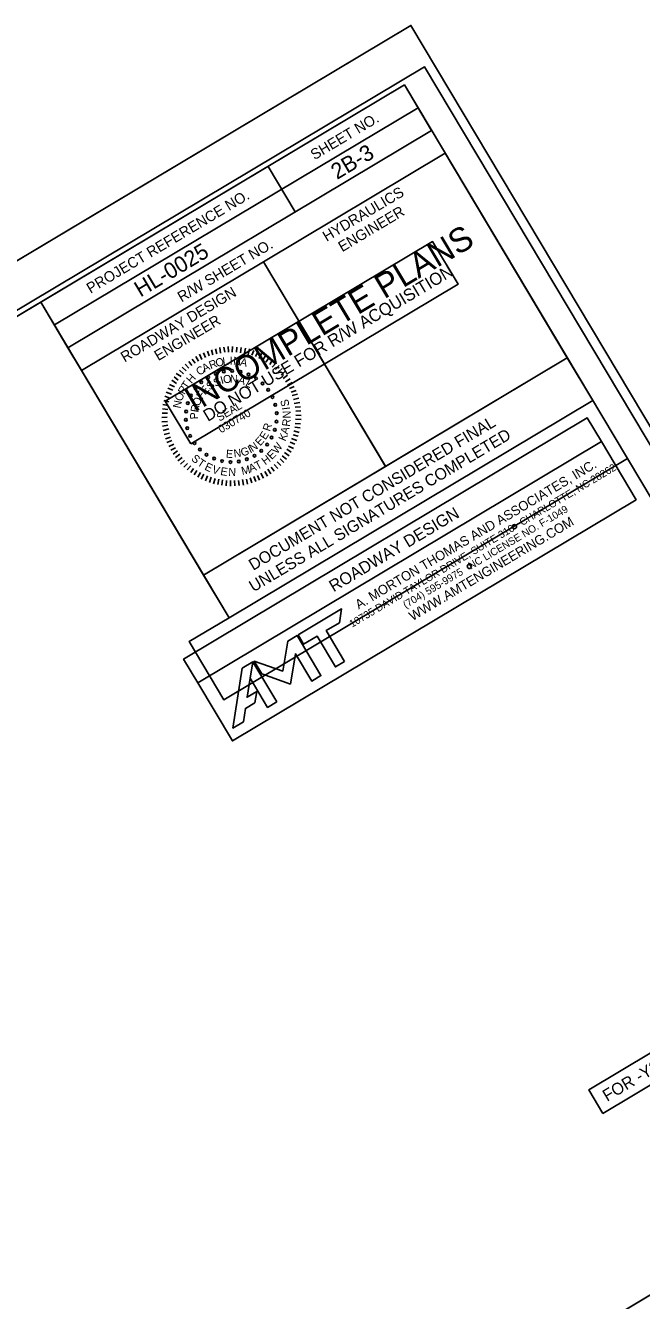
# Model space of a CAD drawing. Extents: x 1487794 to 1489801, y 498102 to 499906.
# Drawn here: x 1489058 to 1489349, y 499304 to 499906 of the extents above; entities that cross this region are included whole.
import ezdxf

# ---------------------------------------------------------------- set-up
doc = ezdxf.new("R2010")
doc.units = 0
for name, color, linetype in [('Exist Profile Cell', 7, 'Continuous'), ('Exist Vertical Profile Ground Line', 7, 'Continuous'), ('Exist Vertical Profile Horizontal Axis Label Major', 7, 'Continuous'), ('Exist Vertical Profile Vertical Axis Label', 7, 'Continuous'), ('Prop Horizontal Alignment Curve and Spiral Data', 7, 'Continuous'), ('Prop Terminator CELL', 7, 'Continuous'), ('Prop Vertical Profile Curve Label', 7, 'Continuous'), ('Prop Vertical Profile Grade Label', 7, 'Continuous'), ('Scratch_Level_5', 7, 'Continuous'), ('Scratch_Level_9', 7, 'Continuous'), ('Sheet Block Title CELL', 7, 'Continuous'), ('Sheet Data Field CELL', 7, 'Continuous'), ('Sheet Layout Profile Border Port 2', 7, 'Continuous'), ('Sheet Plot Border Inside CELL', 7, 'Continuous'), ('Sheet Plot Border Outside CELL', 7, 'Continuous'), ('Sheet Profile CELL', 7, 'Continuous'), ('Sheet Profile Grid Middle CELL', 7, 'Continuous')]:
    doc.layers.add(name, color=color, linetype=linetype)

msp = doc.modelspace()

# ---------------------------------------------------------------- linework, layer by layer
at = {"layer": 'Exist Vertical Profile Ground Line'}
msp.add_lwpolyline([(1488356.6, 498126.17), (1489787.01, 498980.28), (1489246.14, 499886.09), (1487815.74, 499031.98)], close=True, dxfattribs=at)
at = {"layer": 'Exist Vertical Profile Horizontal Axis Label Major'}
msp.add_lwpolyline([(1488355.69, 498102.34), (1489801.12, 498965.41), (1489239.75, 499905.57), (1487794.32, 499042.49)], close=True, dxfattribs=at)
at = {"layer": 'Exist Vertical Profile Vertical Axis Label'}
msp.add_line((1489239.75, 499905.57), (1487794.32, 499042.49), dxfattribs=at)
at = {"layer": 'Prop Horizontal Alignment Curve and Spiral Data'}
msp.add_lwpolyline([(1488273.71, 498661.94), (1489475.73, 499379.68), (1489719.25, 498971.85), (1488517.23, 498254.11)], close=True, dxfattribs=at)
at = {"layer": 'Prop Terminator CELL'}
msp.add_lwpolyline([(1488230.78, 498636.31), (1487948.81, 499108.53), (1489064.93, 499774.97), (1489153.91, 499625.97), (1489135.02, 499614.69), (1489151.4, 499587.25), (1489342.04, 499701.08), (1489518.66, 499405.31)], close=True, dxfattribs=at)
at = {"layer": 'Prop Vertical Profile Curve Label'}
for points in [[(1489139.05, 499595.28), (1489329.69, 499709.11), (1489323, 499720.31), (1489132.36, 499606.48)], [(1489139.05, 499595.28), (1489329.69, 499709.11), (1489346.07, 499681.67), (1489155.43, 499567.84)], [(1489330.45, 499391.96), (1489467.07, 499473.54), (1489460.42, 499484.69), (1489323.8, 499403.11)]]:
    msp.add_lwpolyline(points, close=True, dxfattribs=at)
at = {"layer": 'Prop Vertical Profile Grade Label'}
msp.add_lwpolyline([(1489139.05, 499595.28), (1489329.69, 499709.11), (1489346.07, 499681.67), (1489155.43, 499567.84)], close=True, dxfattribs=at)
for points in [[(1489208.41, 499605.35), (1489199.74, 499619.88), (1489206, 499623.62), (1489207.03, 499630.1), (1489186.52, 499617.85), (1489189.1, 499613.53), (1489195.42, 499617.3), (1489204.09, 499602.77), (1489208.41, 499605.35)], [(1489182.91, 499594.63), (1489185.22, 499608.96), (1489192.9, 499596.09), (1489197.22, 499598.67), (1489185.97, 499617.52), (1489181.65, 499614.94), (1489179.26, 499600.75), (1489165.72, 499605.43), (1489169.3, 499599.43), (1489182.91, 499594.63)], [(1489163.87, 499597.45), (1489165.17, 499605.1), (1489160.12, 499602.09), (1489155.72, 499573.89), (1489160.62, 499576.81), (1489161.6, 499583.15), (1489166.08, 499585.82), (1489167.03, 499591.22), (1489162.39, 499588.45), (1489163.87, 499597.45)], [(1489176.42, 499586.25), (1489165.17, 499605.1), (1489163.87, 499597.45), (1489172.1, 499583.67), (1489176.42, 499586.25)]]:
    msp.add_lwpolyline(points, dxfattribs=at)
for centre in [(1489288.65, 499668.96), (1489267.36, 499650.17)]:
    msp.add_circle(centre, 1, dxfattribs=at)
at = {"layer": 'Scratch_Level_5'}
for p, q in [((1489141.86, 499646.14), (1489313.61, 499748.7)), ((1489313.61, 499748.69), (1489325.66, 499728.51)), ((1489325.65, 499728.52), (1489153.91, 499625.97)), ((1489153.91, 499625.97), (1489141.86, 499646.14))]:
    msp.add_line(p, q, dxfattribs=at)
at = {"layer": 'Scratch_Level_9'}
msp.add_lwpolyline([(1489135.82, 499708.05), (1489123.77, 499728.23), (1489249.98, 499803.59), (1489262.03, 499783.41)], close=True, dxfattribs=at)
at = {"layer": 'Sheet Block Title CELL'}
for p, q in [((1489138.14, 499749.27), (1489139.48, 499747.04)), ((1489139.95, 499750.34), (1489141.02, 499747.96)), ((1489141.73, 499751.06), (1489142.79, 499748.9)), ((1489143.69, 499751.88), (1489144.49, 499749.56)), ((1489145.52, 499752.51), (1489146.15, 499750.09)), ((1489147.46, 499752.97), (1489148.09, 499750.55)), ((1489149.57, 499753.53), (1489149.77, 499750.86)), ((1489151.44, 499753.72), (1489151.85, 499751.28)), ((1489153.4, 499753.95), (1489153.6, 499751.28)), ((1489155.54, 499754.07), (1489155.38, 499751.41)), ((1489157.58, 499753.77), (1489157.32, 499751.29)), ((1489159.57, 499753.56), (1489159.22, 499751.02)), ((1489161.61, 499753.27), (1489161.16, 499750.9)), ((1489163.48, 499752.87), (1489162.91, 499750.31)), ((1489165.5, 499752.21), (1489164.69, 499749.86)), ((1489167.44, 499751.5), (1489166.35, 499749.23)), ((1489169.2, 499750.69), (1489168.12, 499748.42)), ((1489171.02, 499749.8), (1489169.8, 499747.55)), ((1489131.79, 499744.31), (1489133.67, 499742.52)), ((1489133.21, 499745.63), (1489134.87, 499743.82)), ((1489134.86, 499746.96), (1489136.26, 499745)), ((1489136.44, 499748.02), (1489137.93, 499746.11)), ((1489172.8, 499748.77), (1489171.31, 499746.59)), ((1489174.36, 499747.72), (1489173.09, 499745.56)), ((1489176.12, 499746.32), (1489174.3, 499744.3)), ((1489177.61, 499745), (1489175.83, 499743.12)), ((1489179.02, 499743.62), (1489177.13, 499741.91)), ((1489126.78, 499738.06), (1489129.04, 499736.61)), ((1489127.92, 499739.67), (1489129.87, 499738.16)), ((1489128.97, 499741.23), (1489131.23, 499739.78)), ((1489130.46, 499742.82), (1489132.29, 499741.12)), ((1489180.25, 499742.15), (1489178.44, 499740.49)), ((1489181.5, 499740.45), (1489179.42, 499738.86)), ((1489182.66, 499738.69), (1489180.51, 499737.41)), ((1489183.63, 499737.06), (1489181.49, 499735.78)), ((1489124.2, 499732.44), (1489126.65, 499731.46)), ((1489124.96, 499734.29), (1489127.27, 499733.34)), ((1489125.77, 499736.05), (1489128.18, 499734.93)), ((1489184.62, 499735.21), (1489182.46, 499734.15)), ((1489185.53, 499733.3), (1489183.21, 499732.5)), ((1489186.25, 499731.52), (1489183.74, 499730.84)), ((1489122.57, 499726.58), (1489125.08, 499726.09)), ((1489123.06, 499728.5), (1489125.48, 499727.96)), ((1489123.49, 499730.5), (1489125.84, 499729.69)), ((1489186.79, 499729.63), (1489184.28, 499728.95)), ((1489187.3, 499727.61), (1489184.61, 499727.05)), ((1489187.64, 499725.48), (1489185.13, 499725.38)), ((1489122.08, 499720.58), (1489124.64, 499720.59)), ((1489122.21, 499722.51), (1489124.76, 499722.53)), ((1489122.45, 499724.64), (1489124.9, 499724.24)), ((1489187.99, 499719.63), (1489185.29, 499719.65)), ((1489187.94, 499721.46), (1489185.33, 499721.54)), ((1489187.82, 499723.61), (1489185.37, 499723.43)), ((1489122.2, 499718.43), (1489124.87, 499718.63)), ((1489122.43, 499716.48), (1489125.01, 499716.85)), ((1489122.72, 499714.44), (1489125.36, 499715.08)), ((1489123.18, 499712.5), (1489125.68, 499713.18)), ((1489187.01, 499713.46), (1489184.49, 499714.17)), ((1489187.39, 499715.55), (1489184.94, 499715.95)), ((1489187.69, 499717.59), (1489185.17, 499717.71)), ((1489123.83, 499710.44), (1489126.23, 499711.29)), ((1489124.54, 499708.65), (1489126.84, 499709.68)), ((1489125.45, 499706.75), (1489127.73, 499707.99)), ((1489184.3, 499705.9), (1489181.89, 499707.02)), ((1489185.01, 499707.84), (1489182.7, 499708.79)), ((1489185.91, 499709.65), (1489183.37, 499710.58)), ((1489186.48, 499711.62), (1489184.18, 499712.35)), ((1489126.34, 499705.06), (1489128.58, 499706.17)), ((1489127.41, 499703.26), (1489129.46, 499704.71)), ((1489128.52, 499701.59), (1489130.6, 499703.19)), ((1489129.72, 499699.98), (1489131.66, 499701.61)), ((1489179.69, 499699.19), (1489177.95, 499700.94)), ((1489181.05, 499700.81), (1489178.91, 499702.45)), ((1489182.27, 499702.47), (1489180.1, 499703.97)), ((1489183.27, 499704.12), (1489181.15, 499705.53)), ((1489131, 499698.42), (1489132.84, 499700.21)), ((1489132.49, 499697.09), (1489134.25, 499698.84)), ((1489134.07, 499695.82), (1489135.77, 499697.65)), ((1489135.78, 499694.51), (1489137.16, 499696.5)), ((1489137.34, 499693.46), (1489138.66, 499695.54)), ((1489172.05, 499692.88), (1489170.77, 499695.02)), ((1489173.63, 499693.94), (1489172.12, 499696.07)), ((1489175.24, 499695.13), (1489173.76, 499697.04)), ((1489176.89, 499696.47), (1489175.18, 499698.36)), ((1489178.27, 499697.87), (1489176.52, 499699.62)), ((1489139.09, 499692.29), (1489140.44, 499694.5)), ((1489140.76, 499691.43), (1489141.99, 499693.68)), ((1489142.8, 499690.55), (1489143.7, 499692.95)), ((1489144.65, 499689.8), (1489145.36, 499692.31)), ((1489146.49, 499689.26), (1489147.25, 499691.69)), ((1489148.58, 499688.88), (1489148.98, 499691.33)), ((1489150.45, 499688.48), (1489150.74, 499691.1)), ((1489152.49, 499688.18), (1489152.7, 499690.76)), ((1489154.6, 499688.16), (1489154.59, 499690.72)), ((1489156.57, 499688.18), (1489156.42, 499690.77)), ((1489158.58, 499688.33), (1489158.39, 499690.78)), ((1489160.62, 499688.61), (1489160.25, 499691.19)), ((1489162.61, 499688.99), (1489162.06, 499691.46)), ((1489164.62, 499689.72), (1489163.81, 499692.04)), ((1489166.5, 499690.26), (1489165.65, 499692.67)), ((1489168.29, 499690.98), (1489167.32, 499693.19)), ((1489170.19, 499691.88), (1489168.95, 499694.17))]:
    msp.add_line(p, q, dxfattribs=at)
for centre in [(1489155.37, 499742.46), (1489140.78, 499737.14), (1489143.99, 499739.47), (1489147.58, 499741.16), (1489151.41, 499742.17), (1489159.31, 499742.01), (1489163.1, 499740.85), (1489166.61, 499739.01), (1489169.73, 499736.56), (1489135.89, 499730.94), (1489138.05, 499734.26), (1489172.34, 499733.58), (1489134.39, 499727.27), (1489174.36, 499730.17), (1489175.72, 499726.44), (1489133.5, 499719.42), (1489133.58, 499723.38), (1489176.29, 499718.56), (1489176.37, 499722.53), (1489134.15, 499715.51), (1489175.48, 499714.68), (1489135.51, 499711.78), (1489137.53, 499708.37), (1489171.82, 499707.68), (1489173.97, 499711.01), (1489140.14, 499705.39), (1489143.26, 499702.94), (1489146.77, 499701.1), (1489162.29, 499700.79), (1489165.88, 499702.48), (1489169.09, 499704.81), (1489150.56, 499699.94), (1489154.51, 499699.49), (1489158.46, 499699.78)]:
    msp.add_circle(centre, 0.63, dxfattribs=at)
at = {"layer": 'Sheet Data Field CELL'}
msp.add_lwpolyline([(1488230.78, 498636.31), (1489518.66, 499405.31)], dxfattribs=at)
at = {"layer": 'Sheet Plot Border Inside CELL'}
msp.add_lwpolyline([(1489569, 498882.13), (1489325.48, 499289.96), (1489368.41, 499315.59), (1489611.92, 498907.77)], dxfattribs=at)
at = {"layer": 'Sheet Plot Border Outside CELL'}
msp.add_line((1488230.78, 498636.31), (1489518.66, 499405.31), dxfattribs=at)
at = {"layer": 'Sheet Profile CELL'}
msp.add_lwpolyline([(1488273.71, 498661.94), (1489475.73, 499379.68), (1489719.25, 498971.85), (1488517.23, 498254.11)], close=True, dxfattribs=at)
at = {"layer": 'Sheet Profile Grid Middle CELL'}
for p, q in [((1489071.37, 499764.2), (1489243.13, 499866.76)), ((1489077.77, 499753.47), (1489249.53, 499856.03)), ((1489172.32, 499839.04), (1489185.14, 499817.58)), ((1489170.08, 499794.03), (1489227.73, 499697.48)), ((1489077.77, 499753.47), (1489084.18, 499742.73)), ((1488230.78, 498636.31), (1489518.66, 499405.31))]:
    msp.add_line(p, q, dxfattribs=at)
for points in [[(1489236.69, 499877.53), (1487948.81, 499108.53), (1488487.11, 498207.01), (1489774.99, 498976.02)], [(1489064.93, 499774.97), (1489236.69, 499877.53), (1489249.53, 499856.03), (1489077.77, 499753.47)], [(1489170.08, 499794.03), (1489255.94, 499845.29), (1489313.62, 499748.7), (1489227.76, 499697.44)], [(1489084.18, 499742.73), (1489170.08, 499794.03), (1489227.76, 499697.44), (1489141.86, 499646.14)]]:
    msp.add_lwpolyline(points, close=True, dxfattribs=at)

# ---------------------------------------------------------------- texts
at = {"layer": 'Exist Profile Cell'}
for s, p in [('2B-3', (1489204.87, 499832.63)), ('HL-0025', (1489112, 499777.11))]:
    msp.add_text(s, height=7.5, rotation=30.84176, dxfattribs=at).set_placement(p)
at = {"layer": 'Prop Vertical Profile Grade Label'}
for s, height, p in [('10735 DAVID TAYLOR DRIVE, SUITE 310   CHARLOTTE, NC 28262', 3.5, (1489211.96, 499621.23)), ('A. MORTON THOMAS AND ASSOCIATES, INC.', 4.5, (1489215.11, 499629.8)), ('(704) 595-9975   NC LICENSE NO. F-1049', 3.5, (1489237.31, 499630.25)), ('WWW.AMTENGINEERING.COM', 4.5, (1489240.54, 499624.32))]:
    msp.add_text(s, height=height, rotation=30.84127, dxfattribs=at).set_placement(p)
at = {"layer": 'Scratch_Level_5'}
for s, p in [('DOCUMENT NOT CONSIDERED FINAL', (1489165.25, 499648.06)), ('UNLESS ALL SIGNATURES COMPLETED', (1489165.41, 499637.91))]:
    msp.add_text(s, height=5.5, rotation=30.84176, dxfattribs=at).set_placement(p)
at = {"layer": 'Scratch_Level_9'}
for s, height, p in [('INCOMPLETE PLANS', 11.52, (1489137.5, 499722.68)), ('DO NOT USE FOR R/W ACQUISITION', 5.76, (1489143.85, 499718.38))]:
    msp.add_text(s, height=height, rotation=30.84176, dxfattribs=at).set_placement(p)
at = {"layer": 'Sheet Block Title CELL'}
for s, height, rotation, p in [('I', 3.78, 1.64771, (1489154.22, 499745.36)), ('N', 3.78, 355.7456, (1489155.7, 499745.42)), ('C', 3.78, 35.78167, (1489139.91, 499740.07)), ('A', 3.78, 28.81662, (1489142.29, 499741.73)), ('R', 3.78, 20.86331, (1489145.23, 499743.25)), ('O', 3.78, 13.92856, (1489147.98, 499744.31)), ('L', 3.78, 6.58766, (1489151.01, 499745.07)), ('A', 3.78, 347.84683, (1489158.82, 499745.07)), ('T', 3.78, 56.27754, (1489134.17, 499733.5)), ('H', 3.78, 48.5851, (1489136.11, 499736.29)), ('S', 3.76, 35.30978, (1489144.73, 499733.17)), ('S', 3.76, 23.88321, (1489147.42, 499734.89)), ('I', 3.76, 16.32382, (1489150.38, 499736.19)), ('O', 3.76, 8.71664, (1489151.34, 499736.53)), ('N', 3.76, 358.23478, (1489154.22, 499736.97)), ('A', 3.76, 344.78553, (1489157.87, 499736.71)), ('L', 3.76, 332.37406, (1489161.32, 499735.62)), ('O', 3.78, 70.78597, (1489131.58, 499727.88)), ('R', 3.78, 63.0172, (1489132.82, 499731.07)), ('F', 3.76, 57.24171, (1489141.24, 499728.87)), ('E', 3.76, 47.43069, (1489142.56, 499730.94)), ('N', 3.78, 78.90841, (1489130.97, 499724.6)), ('R', 3.76, 80.58955, (1489139.32, 499722.72)), ('O', 3.76, 69.09357, (1489139.82, 499725.58)), ('SEAL', 3.759, 30.84176, (1489149.36, 499718.5)), ('S', 3.78, 103.09964, (1489182.46, 499726.12)), ('I', 3.78, 96.88815, (1489182.72, 499724.31)), ('P', 3.76, 90.9654, (1489139.28, 499719.66)), ('030740', 3.759, 30.84176, (1489150.12, 499712.95)), ('R', 3.78, 81.99207, (1489182.56, 499716.02)), ('N', 3.78, 90.21432, (1489183.01, 499720.06)), ('E', 3.76, 57.99857, (1489171.11, 499709.67)), ('R', 3.76, 71.19102, (1489173.14, 499713.68)), ('K', 3.78, 66.98276, (1489180.47, 499709.01)), ('A', 3.78, 74.36345, (1489181.56, 499712.31)), ('I', 3.76, 26.46634, (1489163.86, 499703.47)), ('N', 3.76, 33.96955, (1489164.89, 499704.09)), ('E', 3.76, 46.64744, (1489168.49, 499706.83)), ('W', 3.78, 52.84752, (1489176.55, 499702.99)), ('S', 3.78, 319.05376, (1489135.67, 499700.64)), ('T', 3.78, 326.46614, (1489138.5, 499698.23)), ('E', 3.76, 355.71095, (1489152.29, 499701.58)), ('N', 3.76, 6.90012, (1489156.24, 499701.6)), ('G', 3.76, 18.323, (1489160.06, 499702.02)), ('H', 3.78, 36.85297, (1489170.98, 499697.88)), ('E', 3.78, 45.00651, (1489174.07, 499700.39)), ('E', 3.78, 334.66425, (1489141.99, 499696.03)), ('V', 3.78, 342.77155, (1489145.56, 499694.46)), ('E', 3.78, 351.073, (1489149.56, 499693.39)), ('N', 3.78, 359.17075, (1489153.5, 499692.91)), ('M', 3.78, 13.17879, (1489160.11, 499693.36)), ('A', 3.78, 21.02392, (1489163.98, 499694.47)), ('T', 3.78, 28.22834, (1489167.19, 499695.74))]:
    msp.add_text(s, height=height, rotation=rotation, dxfattribs=at).set_placement(p)
at = {"layer": 'Sheet Layout Profile Border Port 2'}
for s, p in [('ROADWAY DESIGN', (1489203.25, 499637.93)), ('FOR -Y2- & -Y3- DESIGNS SEE SHEET 5.', (1489332.39, 499397.4))]:
    msp.add_text(s, height=5.625, rotation=30.84176, dxfattribs=at).set_placement(p)
at = {"layer": 'Sheet Profile Grid Middle CELL'}
for s, height, p in [('SHEET NO.', 5, (1489194.24, 499841.93)), ('HYDRAULICS', 5, (1489199.97, 499803.37)), ('PROJECT REFERENCE NO.', 5.0001, (1489088.45, 499778.89)), ('ENGINEER', 5, (1489207.31, 499798.49)), ('R/W SHEET NO.', 5.0001, (1489131.43, 499774.79)), ('ROADWAY DESIGN', 5.0001, (1489104.58, 499746.41)), ('ENGINEER', 5, (1489120.43, 499747.08))]:
    msp.add_text(s, height=height, rotation=30.84176, dxfattribs=at).set_placement(p)

doc.saveas('drawing.dxf')
